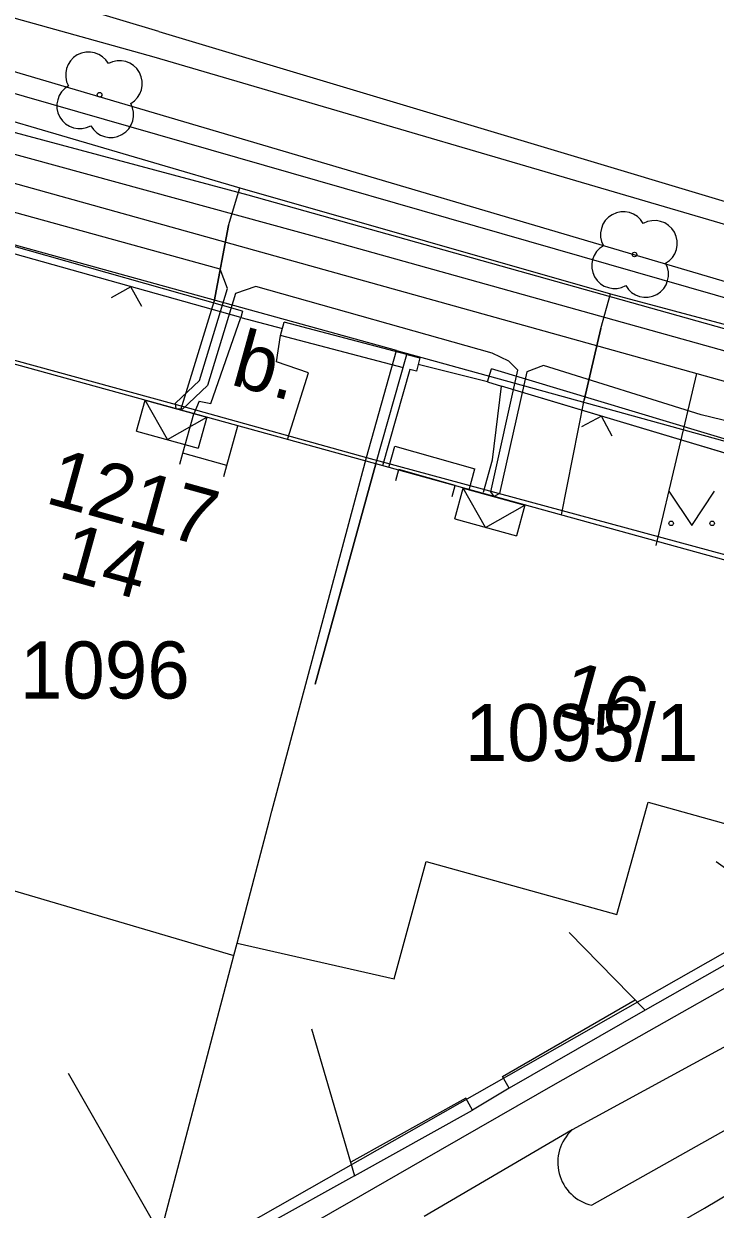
# Model space of a CAD drawing. Extents: x -601580 to 4, y -1204314 to 4.
# Drawn here: x -599854.81 to -599839.67, y -1203333.01 to -1203307.05 of the extents above; entities that cross this region are included whole.
import ezdxf

# ---------------------------------------------------------------- set-up
doc = ezdxf.new("R2010")
doc.units = 0
for name, color, linetype in [('00-EON NN', 7, 'Continuous'), ('00-INNOGY-NTL', 7, 'Continuous'), ('00-KN-HRANICE PARCEL', 7, 'Continuous'), ('00-KN-PARC. CISLA', 7, 'Continuous'), ('00-KN-VNITRNI KRESBA', 7, 'Continuous'), ('00-POLOHOPIS', 7, 'Continuous'), ('00-SITE KOM. KABEL', 7, 'Continuous'), ('00-VAK-VODA-RAD IGIS', 7, 'Continuous'), ('Vrstva 22', 7, 'Continuous'), ('Vrstva 26', 7, 'Continuous'), ('Vrstva 36', 7, 'Continuous'), ('Vrstva 6', 7, 'Continuous'), ('Vrstva 9', 7, 'Continuous')]:
    doc.layers.add(name, color=color, linetype=linetype)

# ---------------------------------------------------------------- blocks, each defined once
blk = doc.blocks.new('3.14_134')
at = {"layer": 'Vrstva 36'}
blk.add_lwpolyline([(-0.5, 0.75), (0, 0), (0.5, 0.75)], dxfattribs=at)
for centre in [(-0.45, 0.05), (0.449, 0.05)]:
    blk.add_circle(centre, 0.05, dxfattribs=at)
blk = doc.blocks.new('3.13_852')
at = {"layer": 'Vrstva 22'}
blk.add_circle((0, 0), 0.05, dxfattribs=at)
for centre, start, end in [((0, 0.5), 359.9999, 179.9999), ((-0.5, 0), 89.9999, 269.9999), ((0.5, 0), 269.9999, 89.9999), ((0, -0.5), 179.9999, 359.9999)]:
    blk.add_arc(centre, 0.5, start, end, dxfattribs=at)
blk = doc.blocks.new('3.13_854')
at = {"layer": 'Vrstva 22'}
blk.add_circle((0, 0), 0.05, dxfattribs=at)
for centre, start, end in [((0, 0.5), 359.9999, 179.9999), ((-0.5, 0), 89.9999, 269.9999), ((0.5, 0), 269.9999, 89.9999), ((0, -0.5), 179.9999, 359.9999)]:
    blk.add_arc(centre, 0.5, start, end, dxfattribs=at)
blk = doc.blocks.new('VCHOD_1336')
at = {"layer": 'Vrstva 6'}
blk.add_line((0, 0.25), (0, 0), dxfattribs=at)
blk = doc.blocks.new('VCHOD_1338')
at = {"layer": 'Vrstva 6'}
blk.add_line((0, 0.25), (0, 0), dxfattribs=at)
blk = doc.blocks.new('VCHOD_1340')
at = {"layer": 'Vrstva 6'}
blk.add_line((-0.001, 0.25), (0, 0), dxfattribs=at)
blk = doc.blocks.new('VCHOD_1342')
at = {"layer": 'Vrstva 6'}
blk.add_line((-0.001, 0.25), (0, 0), dxfattribs=at)
blk = doc.blocks.new('NN630')
at = {"layer": 'Vrstva 9'}
for points in [[(-3, -700), (-703, 0)], [(-703, -700), (-703, 0), (697, 0), (697, -700)], [(-3, -700), (697, 0)], [(-703, -700), (697, -700)]]:
    blk.add_lwpolyline(points, dxfattribs=at)

msp = doc.modelspace()

# ---------------------------------------------------------------- linework, layer by layer
at = {"layer": '00-EON NN'}
for points in [[(-599829.508, -1203319.023), (-599829.62, -1203318.36), (-599835.06, -1203316.81), (-599839.98, -1203315.62), (-599843.43, -1203314.54), (-599843.798, -1203314.678), (-599844.394, -1203317.34), (-599844.512, -1203317.408), (-599844.59, -1203317.302), (-599843.993, -1203314.637), (-599844.19, -1203314.44), (-599844.56, -1203314.27), (-599849.73, -1203312.81), (-599850.173, -1203312.96), (-599850.792, -1203314.974), (-599851.339, -1203315.494), (-599851.477, -1203315.486), (-599851.492, -1203315.362), (-599850.968, -1203314.866), (-599850.348, -1203312.849), (-599850.51, -1203312.43), (-599855.25, -1203311.12)], [(-599877.34, -1203349.66), (-599870.9, -1203345.83), (-599870.536, -1203345.173), (-599870.1, -1203345.38), (-599865.75, -1203343.12), (-599855.75, -1203337.48), (-599847.389, -1203332.689), (-599846.086, -1203331.942), (-599843.17, -1203330.27), (-599836.9, -1203326.72), (-599827.83, -1203321.45), (-599827.33, -1203320.43), (-599827.745, -1203319.318), (-599828.549, -1203319.122), (-599828.929, -1203319.186)]]:
    msp.add_lwpolyline(points, dxfattribs=at)
at = {"layer": '00-INNOGY-NTL'}
msp.add_line((-599840.97, -1203318.48), (-599840.08, -1203314.71), dxfattribs=at)
for points in [[(-599891.321, -1203300.409), (-599872.36, -1203305.71), (-599858.61, -1203309.55), (-599858.43, -1203309.6), (-599840.08, -1203314.71), (-599827.69, -1203318.17), (-599823.19, -1203319.4)], [(-599918.93, -1203378.19), (-599915.5, -1203376.2), (-599912.83, -1203374.69), (-599907.37, -1203371.6), (-599896.09, -1203365.2), (-599892.64, -1203363.24), (-599884.06, -1203358.37), (-599883.12, -1203357.84), (-599875.48, -1203353.51), (-599875.01, -1203353.24), (-599855.55, -1203342.01), (-599842.38, -1203334.41), (-599839.91, -1203332.99), (-599825.89, -1203324.64), (-599823.19, -1203319.4)]]:
    msp.add_lwpolyline(points, dxfattribs=at)
at = {"layer": '00-KN-HRANICE PARCEL'}
for p, q in [((-599846.65, -1203314.21), (-599855.35, -1203311.81)), ((-599846.65, -1203314.21), (-599828.26, -1203319.29)), ((-599837.97, -1203326.54), (-599851.32, -1203334.13))]:
    msp.add_line(p, q, dxfattribs=at)
for points in [[(-599921.72, -1203290.33), (-599917.89, -1203290.73), (-599893.03, -1203296.87), (-599826.78, -1203316.44), (-599809.21, -1203321.87), (-599773.41, -1203332.68), (-599750.39, -1203339.7), (-599709.77, -1203354.1), (-599677.07, -1203366.64), (-599676.9, -1203368.84), (-599676.98, -1203369.55)], [(-599851.32, -1203334.13), (-599851.83, -1203333.61), (-599850.21, -1203327.46), (-599850.14, -1203327.19), (-599849.44, -1203324.52), (-599849.38, -1203324.3), (-599847.31, -1203316.55), (-599846.65, -1203314.21)]]:
    msp.add_lwpolyline(points, dxfattribs=at)
at = {"layer": '00-KN-VNITRNI KRESBA'}
for p, q in [((-599855.97, -1203314.16), (-599851.18, -1203315.47)), ((-599851.18, -1203315.47), (-599847.31, -1203316.55)), ((-599847.31, -1203316.55), (-599835.97, -1203319.63)), ((-599856.55, -1203325.59), (-599850.21, -1203327.46))]:
    msp.add_line(p, q, dxfattribs=at)
msp.add_lwpolyline([(-599850.14, -1203327.19), (-599846.7, -1203327.97), (-599846, -1203325.4), (-599841.83, -1203326.56), (-599841.14, -1203324.1), (-599837.58, -1203325.09)], dxfattribs=at)
at = {"layer": '00-POLOHOPIS'}
for p, q in [((-599851.852, -1203307.226), (-599864.558, -1203303.398)), ((-599848.154, -1203311.795), (-599871.854, -1203305.309)), ((-599851.852, -1203307.226), (-599833.95, -1203312.604)), ((-599834.862, -1203315.505), (-599848.154, -1203311.795)), ((-599850.061, -1203313.489), (-599855.003, -1203312.1)), ((-599850.717, -1203315.373), (-599850.061, -1203313.489)), ((-599849.19, -1203313.879), (-599849.114, -1203313.589)), ((-599849.282, -1203314.459), (-599849.19, -1203313.879)), ((-599848.577, -1203314.7), (-599849.282, -1203314.459)), ((-599844.66, -1203314.896), (-599846.178, -1203314.518)), ((-599844.66, -1203314.896), (-599844.574, -1203314.609)), ((-599834.896, -1203317.526), (-599844.574, -1203314.609)), ((-599849.028, -1203316.136), (-599848.577, -1203314.7)), ((-599844.66, -1203314.896), (-599844.356, -1203314.988)), ((-599844.552, -1203316.6), (-599844.356, -1203314.988)), ((-599834.979, -1203317.803), (-599844.356, -1203314.988)), ((-599850.974, -1203315.319), (-599851.086, -1203315.594)), ((-599850.974, -1203315.319), (-599850.717, -1203315.373)), ((-599851.326, -1203316.461), (-599851.086, -1203315.594)), ((-599850.367, -1203316.726), (-599850.127, -1203315.859)), ((-599850.367, -1203316.726), (-599851.326, -1203316.461)), ((-599850.367, -1203316.726), (-599851.326, -1203316.461)), ((-599846.818, -1203316.773), (-599846.69, -1203316.308)), ((-599846.69, -1203316.308), (-599844.936, -1203316.801)), ((-599844.75, -1203317.313), (-599844.552, -1203316.6)), ((-599845.364, -1203317.165), (-599846.602, -1203316.818)), ((-599845.062, -1203317.257), (-599844.936, -1203316.801)), ((-599829.08, -1203323.806), (-599842.809, -1203331.276)), ((-599828.951, -1203325.377), (-599842.378, -1203332.925)), ((-599844.183, -1203330.365), (-599844.99, -1203330.846)), ((-599842.809, -1203331.276), (-599846.045, -1203333.171))]:
    msp.add_line(p, q, dxfattribs=at)
for points in [[(-599850.02, -1203313.345), (-599855.127, -1203311.905), (-599855.815, -1203314.287)], [(-599850.061, -1203313.489), (-599855.003, -1203312.1)], [(-599852.226, -1203313.244), (-599852.468, -1203312.813), (-599852.899, -1203313.055)], [(-599850.02, -1203313.345), (-599850.061, -1203313.489), (-599849.151, -1203313.73)], [(-599846.424, -1203314.298), (-599849.114, -1203313.589)], [(-599846.5, -1203314.588), (-599849.19, -1203313.879)], [(-599848.433, -1203321.514), (-599847.105, -1203316.694), (-599855.815, -1203314.287), (-599857.147, -1203319.106)], [(-599847.105, -1203316.694), (-599846.424, -1203314.298), (-599846.14, -1203314.373), (-599846.216, -1203314.663), (-599846.361, -1203314.625), (-599846.96, -1203316.734)], [(-599834.979, -1203317.803), (-599844.356, -1203314.988)], [(-599841.928, -1203316.082), (-599842.162, -1203315.647), (-599842.598, -1203315.881)], [(-599836.54, -1203322.63), (-599835.81, -1203319.806), (-599847.105, -1203316.694), (-599848.433, -1203321.514)], [(-599839.656, -1203325.399), (-599837.803, -1203326.72), (-599841.208, -1203328.651), (-599842.87, -1203326.954)], [(-599841.208, -1203328.651), (-599844.183, -1203330.365), (-599844.333, -1203330.105), (-599841.425, -1203328.43)], [(-599848.514, -1203329.066), (-599847.568, -1203332.28), (-599851.352, -1203334.383), (-599853.834, -1203330.042)], [(-599847.568, -1203332.28), (-599844.99, -1203330.846), (-599845.136, -1203330.584), (-599847.655, -1203331.985)]]:
    msp.add_lwpolyline(points, dxfattribs=at)
msp.add_arc((-599842.159, -1203331.987), 0.963, 132.4485, 256.847, dxfattribs=at)
at = {"layer": '00-SITE KOM. KABEL'}
for points in [[(-599885.06, -1203301.1), (-599871.77, -1203304.86), (-599865.55, -1203306.61), (-599849.91, -1203310.8), (-599834.77, -1203315.05), (-599827.22, -1203317.11), (-599827.01, -1203317.85), (-599826.9, -1203322.56), (-599826.77, -1203323.56), (-599822.73, -1203329.86)], [(-599861.43, -1203307.32), (-599850.08, -1203310.65)], [(-599851.37, -1203315.51), (-599850.64, -1203313.14), (-599850.33, -1203311.47), (-599850.08, -1203310.65)], [(-599850.08, -1203310.65), (-599841.97, -1203312.97)], [(-599850.33, -1203311.47), (-599850.64, -1203313.14)], [(-599843.04, -1203317.81), (-599842.54, -1203315.3), (-599842.18, -1203313.73), (-599841.97, -1203312.97)], [(-599841.97, -1203312.97), (-599835, -1203314.83), (-599831.14, -1203315.82), (-599827.08, -1203317.18), (-599826.89, -1203317.95), (-599826.11, -1203319.45), (-599826.53, -1203321.27), (-599827.31, -1203322.05), (-599832.42, -1203324.87), (-599831.41, -1203326.55), (-599827.19, -1203332.98)], [(-599842.18, -1203313.73), (-599842.54, -1203315.3)]]:
    msp.add_lwpolyline(points, dxfattribs=at)
at = {"layer": '00-VAK-VODA-RAD IGIS'}
for points in [[(-599720.355, -1203347.776), (-599729.23, -1203344.714), (-599770.31, -1203331.391), (-599796.664, -1203323.541), (-599826.579, -1203315.23), (-599851.958, -1203307.785), (-599870.565, -1203302.595), (-599896.257, -1203294.737), (-599907.177, -1203291.811)], [(-599902.046, -1203295.125), (-599868.378, -1203304.731), (-599831.703, -1203315.287), (-599809.417, -1203321.634), (-599778.543, -1203330.362), (-599752.729, -1203340.898), (-599712.522, -1203351.656), (-599694.336, -1203358.224), (-599621.861, -1203382.557), (-599578.525, -1203396.236), (-599556.78, -1203403.208)]]:
    msp.add_lwpolyline(points, dxfattribs=at)

# ---------------------------------------------------------------- block references
at = {"layer": '00-POLOHOPIS'}
for name, p, xscale, yscale, rotation in [('3.13_854', (-599853.152, -1203308.609), 0.9999988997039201, 0.99999889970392, 29.222996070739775), ('3.13_852', (-599841.441, -1203312.108), 0.9999988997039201, 0.99999889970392, 29.222996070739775), ('VCHOD_1336', (-599851.326, -1203316.461), 1.00000197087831, 1.00000197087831, 164.5528816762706), ('VCHOD_1338', (-599850.367, -1203316.726), 1.00000197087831, 1.00000197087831, 164.5528816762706), ('VCHOD_1340', (-599846.602, -1203316.818), 0.99999979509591, 0.9999997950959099, 164.3423689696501), ('VCHOD_1342', (-599845.364, -1203317.165), 0.99999979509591, 0.9999997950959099, 164.3423689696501)]:
    msp.add_blockref(name, p, dxfattribs=dict(at, xscale=xscale, yscale=yscale, rotation=rotation))
msp.add_blockref('3.14_134', (-599840.189, -1203318.043), dxfattribs=at)
at = {"layer": 'Vrstva 26', "xscale": 0.001}
for p, yscale, rotation in [((-599851.477, -1203315.486), 0.0010000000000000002, -15.382136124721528), ((-599844.512, -1203317.408), 0.001, -15.403944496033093)]:
    msp.add_blockref('NN630', p, dxfattribs=dict(at, yscale=yscale, rotation=rotation))

# ---------------------------------------------------------------- texts
at = {"layer": '00-KN-PARC. CISLA'}
for s, p in [('1096', (-599854.897, -1203321.83)), ('1095/1', (-599845.155, -1203323.2))]:
    msp.add_text(s, height=1.25, dxfattribs=at).set_placement(p)
at = {"layer": '00-POLOHOPIS'}
for s, rotation, p in [('b.', 344.5519, (-599850.314, -1203314.946)), ('1217', 344.5519, (-599854.371, -1203317.539)), ('14', 344.5519, (-599854.091, -1203319.172)), ('16', 344.596, (-599843.157, -1203322.19))]:
    msp.add_text(s, height=1.25, rotation=rotation, dxfattribs=at).set_placement(p)

doc.saveas('drawing.dxf')
